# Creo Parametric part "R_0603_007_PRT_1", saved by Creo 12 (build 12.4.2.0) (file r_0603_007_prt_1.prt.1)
Units: Custom; MM, KILOGRAM, SECS

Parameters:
  PTC_WM_ITERATION = "0"
  PTC_WM_VERSION = "-.0"
  PTC_WM_LIFECYCLE_STATE = "In Work"
  PTC_WM_LIFECYCLE = "MO_CADDocument"
  PTC_WM_CREATED_BY = "Maximilian Roepper (Z0017RMS: MO)"
  PTC_WM_CREATED_ON = "18-Sep-26 11:36:42 AM"
  PTC_WM_MODIFIED_BY = "Maximilian Roepper (Z0017RMS: MO)"
  PTC_WM_MODIFIED_ON = "18-Sep-26 11:36:46 AM"
  PDMLINKNUMBER = "PDM000071455197"
  PTC_WM_NAME = "r_0603_007_prt_1.prt"
  PTC_WM_NUMBER = "PDM000071455197"

Other parameters: WEIGHT, WEIGHT_FACTOR, WEIGHT_ADD, _MASS_TEMP, _DIFF_TEMP, MC_ERRORS, SUPPLIER

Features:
  1. coordinate system
  2. datum plane "PRT_YZ"
  3. datum plane "PRT_XY"
  4. datum plane "PRT_XZ"
  5. coordinate system
  6. datum axis
  7. datum axis
  8. datum axis
  9. coordinate system
  10. imported feature
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
Other named items: PRT, SIEMENS_MO, DRW_VIEW_ORG, PRT_X, PRT_Y, PRT_Z, CS0, ROUGH_GROB

Layers: 00_STD_CSYS-KSYS, 01_STD_PLANES-EBENEN, 02_STD_AXES-ACHSEN, 03_STD_CSYS-KSYS, 24_IMPORT_FEAT-IMPORT_KE

Surfaces: 18 plane, 8 cylinder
